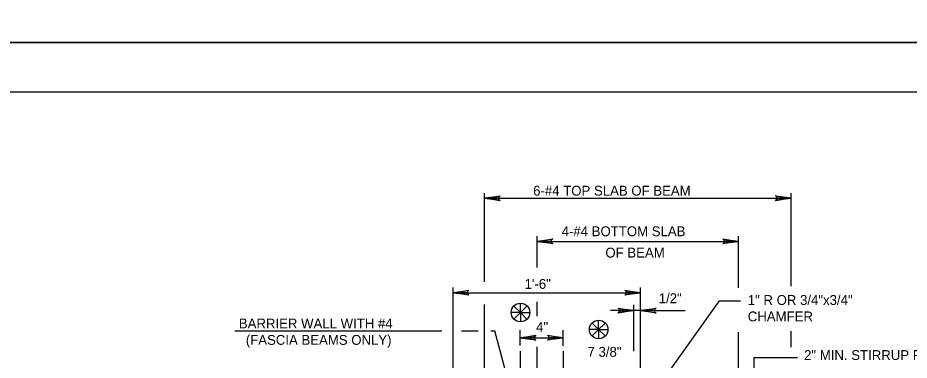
# Model space of a CAD drawing. Extents: x 642009 to 642864, y 298232 to 300014.
# Drawn here: x 642437.9 to 642709.1, y 298729.1 to 298833.3 of the extents above; entities that cross this region are included whole.
import ezdxf

# ---------------------------------------------------------------- set-up
doc = ezdxf.new("R2010")
doc.units = 0
for name, color, linetype in [('1', 7, 'Continuous'), ('10', 7, 'Continuous'), ('2', 7, 'Continuous'), ('22', 7, 'Continuous'), ('PLT-BNDY', 7, 'Continuous')]:
    doc.layers.add(name, color=color, linetype=linetype)

msp = doc.modelspace()

# ---------------------------------------------------------------- linework, layer by layer
at = {"layer": '1'}
for p, q in [((642590.83, 298743.56), (642588.86, 298745.53)), ((642590.83, 298743.56), (642590.83, 298746.34)), ((642590.83, 298743.56), (642592.8, 298745.53)), ((642590.83, 298743.56), (642588.05, 298743.56)), ((642590.83, 298743.56), (642588.86, 298741.59)), ((642590.83, 298743.56), (642590.83, 298740.77)), ((642590.83, 298743.56), (642592.8, 298741.59)), ((642590.83, 298743.56), (642593.62, 298743.56)), ((642614.63, 298738.39), (642612.66, 298740.36)), ((642614.63, 298738.39), (642614.63, 298741.17)), ((642614.63, 298738.39), (642616.6, 298740.36)), ((642614.63, 298738.39), (642611.84, 298738.39)), ((642614.63, 298738.39), (642612.66, 298736.42)), ((642614.63, 298738.39), (642614.63, 298735.6)), ((642614.63, 298738.39), (642616.6, 298736.42)), ((642614.63, 298738.39), (642617.42, 298738.39))]:
    msp.add_line(p, q, dxfattribs=at)
for centre in [(642590.84, 298743.57), (642614.64, 298738.4)]:
    msp.add_circle(centre, 2.83, dxfattribs=at)
at = {"layer": '10'}
for p, q in [((642590.78, 298731.79), (642590.78, 298676.82)), ((642603.84, 298731.79), (642603.84, 298676.82))]:
    msp.add_line(p, q, dxfattribs=at)
at = {"layer": '2'}
msp.add_line((642048.66, 298810.82), (642834.66, 298810.82), dxfattribs=at)
at = {"layer": '22'}
for p, q in [((642579.9, 298752.92), (642579.9, 298779.95)), ((642579.9, 298778.39), (642673.17, 298778.39)), ((642673.17, 298751.64), (642673.17, 298779.95)), ((642595.91, 298757.24), (642595.91, 298766.78)), ((642657.17, 298751.12), (642657.17, 298766.78)), ((642595.91, 298765.22), (642657.17, 298765.22)), ((642570.34, 298717.91), (642570.34, 298751.16)), ((642627.33, 298717.54), (642627.33, 298751.16)), ((642570.34, 298749.6), (642627.33, 298749.6)), ((642579.9, 298709.99), (642579.9, 298746)), ((642595.91, 298742.5), (642595.91, 298746.84)), ((642625.32, 298710.64), (642651.44, 298747.17)), ((642625.33, 298731.79), (642625.33, 298745.9)), ((642651.44, 298747.17), (642657.77, 298747.17)), ((642620.8, 298744.17), (642618.28, 298744.17)), ((642620.8, 298744.17), (642625.33, 298744.17)), ((642627.33, 298744.17), (642625.33, 298744.17)), ((642627.33, 298744.17), (642641, 298744.17)), ((642503.86, 298737.98), (642566.91, 298737.98)), ((642572.94, 298737.98), (642577.93, 298737.98)), ((642581.82, 298737.98), (642583, 298737.98)), ((642595.11, 298692.86), (642583, 298737.98)), ((642590.78, 298733.5), (642590.78, 298738.2)), ((642603.84, 298733.41), (642603.84, 298738.2)), ((642657.17, 298645.37), (642657.17, 298737.58)), ((642673.17, 298732.97), (642673.17, 298737.84)), ((642590.78, 298735.87), (642603.84, 298735.87)), ((642595.91, 298709.47), (642595.91, 298733.11)), ((642661.88, 298729.82), (642661.88, 298654.55)), ((642661.88, 298729.82), (642675.12, 298729.82))]:
    msp.add_line(p, q, dxfattribs=at)
for points in [[(642584.44, 298777.82), (642584.27, 298778.14), (642579.9, 298778.39), (642584.44, 298777.82), (642584.67, 298777.62), (642579.9, 298778.39), (642584.27, 298778.6), (642584.43, 298778.93), (642579.9, 298778.39), (642584.67, 298779.14), (642584.43, 298778.93)], [(642668.63, 298778.96), (642668.8, 298778.63), (642673.17, 298778.39), (642668.63, 298778.96), (642668.4, 298779.15), (642673.17, 298778.39), (642668.81, 298778.17), (642668.65, 298777.84), (642673.17, 298778.39), (642668.4, 298777.63), (642668.65, 298777.84)], [(642600.45, 298764.65), (642600.28, 298764.98), (642595.91, 298765.22), (642600.45, 298764.65), (642600.68, 298764.45), (642595.91, 298765.22), (642600.27, 298765.44), (642600.43, 298765.76), (642595.91, 298765.22), (642600.68, 298765.98), (642600.43, 298765.76)], [(642652.63, 298765.79), (642652.8, 298765.46), (642657.17, 298765.22), (642652.63, 298765.79), (642652.39, 298765.99), (642657.17, 298765.22), (642652.8, 298765), (642652.64, 298764.68), (642657.17, 298765.22), (642652.39, 298764.46), (642652.64, 298764.68)], [(642574.88, 298749.03), (642574.71, 298749.36), (642570.34, 298749.6), (642574.88, 298749.03), (642575.12, 298748.83), (642570.34, 298749.6), (642574.71, 298749.81), (642574.87, 298750.14), (642570.34, 298749.6), (642575.12, 298750.36), (642574.87, 298750.14)], [(642622.79, 298750.17), (642622.96, 298749.84), (642627.33, 298749.6), (642622.79, 298750.17), (642622.56, 298750.37), (642627.33, 298749.6), (642622.97, 298749.38), (642622.81, 298749.06), (642627.33, 298749.6), (642622.56, 298748.84), (642622.81, 298749.06)], [(642620.79, 298744.74), (642620.95, 298744.41), (642625.33, 298744.17), (642620.79, 298744.74), (642620.55, 298744.94), (642625.33, 298744.17), (642620.96, 298743.95), (642620.8, 298743.63), (642625.33, 298744.17), (642620.55, 298743.41), (642620.8, 298743.63)], [(642631.87, 298743.6), (642631.7, 298743.93), (642627.33, 298744.17), (642631.87, 298743.6), (642632.11, 298743.4), (642627.33, 298744.17), (642631.7, 298744.39), (642631.86, 298744.71), (642627.33, 298744.17), (642632.11, 298744.93), (642631.86, 298744.71)], [(642595.32, 298735.3), (642595.15, 298735.63), (642590.78, 298735.87), (642595.32, 298735.3), (642595.55, 298735.1), (642590.78, 298735.87), (642595.15, 298736.08), (642595.31, 298736.41), (642590.78, 298735.87), (642595.55, 298736.63), (642595.31, 298736.41)], [(642599.3, 298736.44), (642599.47, 298736.11), (642603.84, 298735.87), (642599.3, 298736.44), (642599.07, 298736.64), (642603.84, 298735.87), (642599.48, 298735.65), (642599.32, 298735.33), (642603.84, 298735.87), (642599.07, 298735.11), (642599.32, 298735.33)]]:
    msp.add_lwpolyline(points, dxfattribs=at)
at = {"layer": 'PLT-BNDY'}
for points in [[(642008.66, 299419.82), (642849.66, 299419.82), (642849.66, 298825.82), (642008.66, 298825.82)], [(642008.66, 298825.82), (642849.66, 298825.82), (642849.66, 298231.82), (642008.66, 298231.82)]]:
    msp.add_lwpolyline(points, close=True, dxfattribs=at)

# ---------------------------------------------------------------- texts
at = {"layer": '22'}
for s, height, p in [('6-#4 TOP SLAB OF BEAM', 2.9997, (642594.7, 298779.17)), ('4-#4 BOTTOM SLAB', 2.9997, (642603.37, 298766.81)), ('OF BEAM', 3, (642616.69, 298760.31)), ('1\'-6"', 3, (642592.09, 298750.78)), ('BARRIER WALL WITH #4', 2.9997, (642505.13, 298738.73)), ('4"', 3, (642595.61, 298737.68)), ('(FASCIA BEAMS ONLY)', 2.9997, (642507.25, 298733.73)), ('7 3/8"', 3, (642611.24, 298730.09))]:
    msp.add_text(s, height=height, dxfattribs=at).set_placement(p)
for s, height, p in [('1/2"', 3, (642632.91, 298746.41)), ('1" R OR 3/4"x3/4"', 2.9997, (642660.01, 298745.88)), ('CHAMFER', 3, (642660.01, 298740.88)), ('2" MIN. STIRRUP PROJECTION', 2.9997, (642677.15, 298729.11))]:
    msp.add_text(s, height=height, rotation=360, dxfattribs=at).set_placement(p)

doc.saveas('drawing.dxf')
